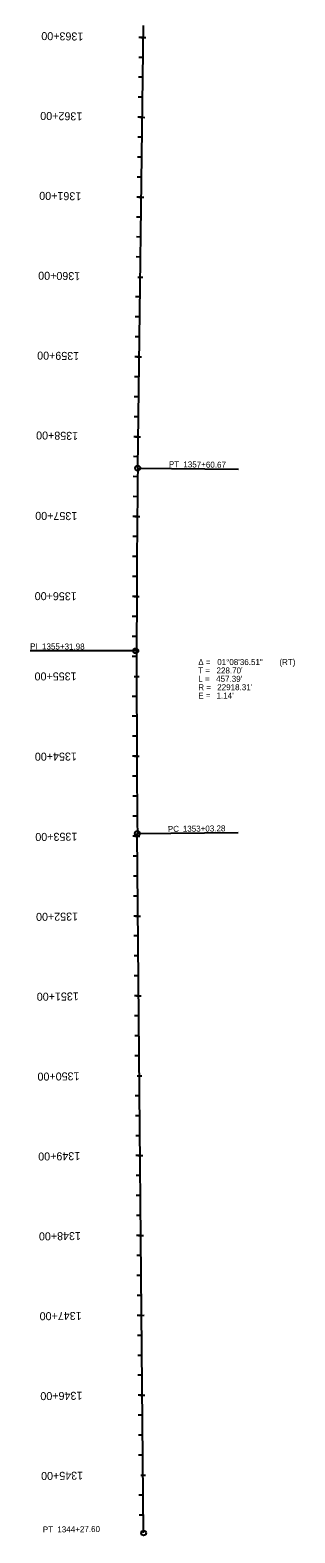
# Model space of a CAD drawing. Extents: x 19548215 to 19548727, y 7547983 to 7562114.
# Drawn here: x 19548243 to 19548574, y 7556426 to 7558308 of the extents above; entities that cross this region are included whole.
import ezdxf

# ---------------------------------------------------------------- set-up
doc = ezdxf.new("R2010")
doc.units = 0
for name, color, linetype in [('Contours Major', 7, 'Continuous'), ('Contours Minor', 7, 'Continuous'), ('Default', 7, 'Continuous'), ('TextAlignment', 7, 'Continuous'), ('TextAlignmentSml', 7, 'Continuous')]:
    doc.layers.add(name, color=color, linetype=linetype)

msp = doc.modelspace()

# ---------------------------------------------------------------- linework, layer by layer
at = {"layer": 'Contours Major'}
for p, q in [((19548384.7, 7558298.7), (19548379.3, 7558298.7)), ((19548383.4, 7558198.7), (19548378, 7558198.7)), ((19548382.1, 7558098.7), (19548376.7, 7558098.8)), ((19548377.8, 7557998.7), (19548383.9, 7557998.6)), ((19548379.5, 7557898.7), (19548374.1, 7557898.8)), ((19548378.2, 7557798.7), (19548372.7, 7557798.8)), ((19548377.1, 7557698.7), (19548371.6, 7557698.8)), ((19548376.5, 7557598.7), (19548371, 7557598.7)), ((19548373.3, 7557498.7), (19548379.4, 7557498.7)), ((19548376.6, 7557398.7), (19548371.1, 7557398.7)), ((19548377.3, 7557298.7), (19548371.8, 7557298.7)), ((19548378.2, 7557198.7), (19548372.7, 7557198.7)), ((19548379.1, 7557098.7), (19548373.6, 7557098.7)), ((19548376.9, 7556998.7), (19548383, 7556998.8)), ((19548380.9, 7556898.7), (19548375.4, 7556898.7)), ((19548381.8, 7556798.7), (19548376.3, 7556798.7)), ((19548382.7, 7556698.7), (19548377.2, 7556698.7)), ((19548383.6, 7556598.7), (19548378.1, 7556598.7)), ((19548381.4, 7556498.7), (19548387.5, 7556498.8))]:
    msp.add_line(p, q, dxfattribs=at)
at = {"layer": 'Contours Minor'}
for p, q in [((19548377.7, 7557759.4), (19548384.9, 7558313.4)), ((19548385.1, 7556426.3), (19548377.2, 7557302))]:
    msp.add_line(p, q, dxfattribs=at)
msp.add_arc((19571294.6, 7557508.5), 22918.3, 179.37292, 180.51639, dxfattribs=at)
at = {"layer": 'Default'}
msp.add_line((19548385.1, 7556426.3), (19548377.2, 7557302), dxfattribs=at)
msp.add_arc((19571294.6, 7557508.5), 22918.3, 179.37292, 180.51639, dxfattribs=at)
at = {"layer": 'TextAlignment'}
for p, q in [((19548377.7, 7557759.4), (19548503.7, 7557758)), ((19548503.7, 7557758), (19548503.7, 7557758)), ((19548375.2, 7557530.7), (19548243.2, 7557530.8)), ((19548243.2, 7557530.8), (19548243.2, 7557530.8)), ((19548377.2, 7557302), (19548503.2, 7557303.1)), ((19548503.2, 7557303.1), (19548503.2, 7557303.1))]:
    msp.add_line(p, q, dxfattribs=at)
for centre in [(19548377.7, 7557759.4), (19548375.2, 7557530.7), (19548377.2, 7557302), (19548385.1, 7556426.3)]:
    msp.add_circle(centre, 3.12, dxfattribs=at)
at = {"layer": 'TextAlignmentSml'}
for p, q in [((19548381.7, 7558298.7), (19548387.8, 7558298.6)), ((19548384.4, 7558273.7), (19548379, 7558273.7)), ((19548384.1, 7558248.7), (19548378.6, 7558248.7)), ((19548383.8, 7558223.7), (19548378.3, 7558223.7)), ((19548380.4, 7558198.7), (19548386.5, 7558198.6)), ((19548383.1, 7558173.7), (19548377.7, 7558173.7)), ((19548382.8, 7558148.7), (19548377.3, 7558148.7)), ((19548382.5, 7558123.7), (19548377, 7558123.8)), ((19548379.1, 7558098.7), (19548385.2, 7558098.6)), ((19548381.8, 7558073.7), (19548376.3, 7558073.8)), ((19548381.5, 7558048.7), (19548376, 7558048.8)), ((19548381.1, 7558023.7), (19548375.7, 7558023.8)), ((19548377.8, 7557998.7), (19548383.9, 7557998.6)), ((19548380.5, 7557973.7), (19548375, 7557973.8)), ((19548380.2, 7557948.7), (19548374.7, 7557948.8)), ((19548379.8, 7557923.7), (19548374.4, 7557923.8)), ((19548376.5, 7557898.7), (19548382.6, 7557898.7)), ((19548379.2, 7557873.7), (19548373.7, 7557873.8)), ((19548378.9, 7557848.7), (19548373.4, 7557848.8)), ((19548378.5, 7557823.7), (19548373.1, 7557823.8)), ((19548375.1, 7557798.7), (19548381.3, 7557798.7)), ((19548377.9, 7557773.7), (19548372.4, 7557773.8)), ((19548377.6, 7557748.7), (19548372.1, 7557748.8)), ((19548377.3, 7557723.7), (19548371.9, 7557723.8)), ((19548374, 7557698.7), (19548380.2, 7557698.7)), ((19548376.9, 7557673.7), (19548371.5, 7557673.8)), ((19548376.7, 7557648.7), (19548371.3, 7557648.7)), ((19548376.6, 7557623.7), (19548371.1, 7557623.7)), ((19548373.4, 7557598.7), (19548379.6, 7557598.7)), ((19548376.4, 7557573.7), (19548370.9, 7557573.7)), ((19548376.4, 7557548.7), (19548370.9, 7557548.7)), ((19548376.3, 7557523.7), (19548370.9, 7557523.7)), ((19548373.3, 7557498.7), (19548379.4, 7557498.7)), ((19548376.3, 7557473.7), (19548370.9, 7557473.7)), ((19548376.4, 7557448.7), (19548370.9, 7557448.7)), ((19548376.5, 7557423.7), (19548371, 7557423.7)), ((19548373.5, 7557398.7), (19548379.6, 7557398.7)), ((19548376.7, 7557373.7), (19548371.3, 7557373.7)), ((19548376.9, 7557348.7), (19548371.4, 7557348.7)), ((19548377.1, 7557323.7), (19548371.6, 7557323.7)), ((19548374.2, 7557298.7), (19548380.3, 7557298.7)), ((19548377.5, 7557273.7), (19548372, 7557273.7)), ((19548377.7, 7557248.7), (19548372.3, 7557248.7)), ((19548378, 7557223.7), (19548372.5, 7557223.7)), ((19548375.1, 7557198.7), (19548381.2, 7557198.7)), ((19548378.4, 7557173.7), (19548372.9, 7557173.7)), ((19548378.6, 7557148.7), (19548373.2, 7557148.7)), ((19548378.9, 7557123.7), (19548373.4, 7557123.7)), ((19548376, 7557098.7), (19548382.1, 7557098.8)), ((19548379.3, 7557073.7), (19548373.8, 7557073.7)), ((19548379.5, 7557048.7), (19548374.1, 7557048.7)), ((19548379.8, 7557023.7), (19548374.3, 7557023.7)), ((19548376.9, 7556998.7), (19548383, 7556998.8)), ((19548380.2, 7556973.7), (19548374.7, 7556973.7)), ((19548380.4, 7556948.7), (19548375, 7556948.7)), ((19548380.7, 7556923.7), (19548375.2, 7556923.7)), ((19548377.8, 7556898.7), (19548383.9, 7556898.8)), ((19548381.1, 7556873.7), (19548375.6, 7556873.7)), ((19548381.3, 7556848.7), (19548375.9, 7556848.7)), ((19548381.6, 7556823.7), (19548376.1, 7556823.7)), ((19548378.7, 7556798.7), (19548384.8, 7556798.8)), ((19548382, 7556773.7), (19548376.5, 7556773.7)), ((19548382.2, 7556748.7), (19548376.8, 7556748.7)), ((19548382.5, 7556723.7), (19548377, 7556723.7)), ((19548379.6, 7556698.7), (19548385.7, 7556698.8)), ((19548382.9, 7556673.7), (19548377.5, 7556673.7)), ((19548383.1, 7556648.7), (19548377.7, 7556648.7)), ((19548383.4, 7556623.7), (19548377.9, 7556623.7)), ((19548380.5, 7556598.7), (19548386.6, 7556598.8)), ((19548383.8, 7556573.7), (19548378.4, 7556573.7)), ((19548384, 7556548.7), (19548378.6, 7556548.7)), ((19548384.3, 7556523.7), (19548378.8, 7556523.7)), ((19548381.4, 7556498.7), (19548387.5, 7556498.8)), ((19548384.7, 7556473.8), (19548379.3, 7556473.7)), ((19548384.9, 7556448.8), (19548379.5, 7556448.7))]:
    msp.add_line(p, q, dxfattribs=at)

# ---------------------------------------------------------------- texts
at = {"layer": 'Contours Major'}
for s, rotation, p in [('1360+00', 179.2501, (19548305.9, 7558004.7)), ('1355+00', 180.0246, (19548301.3, 7557503.7)), ('1350+00', 180.5164, (19548304.9, 7557003.1)), ('1345+00', 180.5164, (19548309.4, 7556503.1))]:
    msp.add_text(s, height=10.02, rotation=rotation, dxfattribs=at).set_placement(p)
at = {"layer": 'TextAlignment'}
for s, rotation, p in [('PT', 359.3729, (19548416.6, 7557760.6)), ('1357+60.67', 359.3729, (19548434.7, 7557760.4)), ('PI ', 359.9447, (19548243.2, 7557532.5)), ('1355+31.98', 359.9447, (19548258.1, 7557532.4)), ('PC', 0.5164, (19548415.4, 7557304)), ('1353+03.28', 0.5164, (19548434.1, 7557304.2)), ('PT', 0.5164, (19548259.1, 7556426.9)), ('1344+27.60', 0.5164, (19548277.3, 7556427))]:
    msp.add_text(s, height=7.5, rotation=rotation, dxfattribs=at).set_placement(p)
for s, p in [('Δ = ', (19548453.4, 7557512.9)), ('01°08\'36.51"', (19548477.1, 7557512.9)), (' (RT)', (19548552, 7557512.9)), ('T = ', (19548453.4, 7557502.4)), ('L = ', (19548453.4, 7557491.9)), ("457.39'", (19548475.7, 7557491.9)), ("228.70'", (19548476.2, 7557502.4)), ('R = ', (19548453.4, 7557481.4)), ('E = ', (19548453.4, 7557470.9)), ("1.14'", (19548476.2, 7557470.9)), ("22918.31'", (19548477.1, 7557481.4))]:
    msp.add_text(s, height=7.5, dxfattribs=at).set_placement(p)
at = {"layer": 'TextAlignmentSml'}
for s, rotation, p in [('1363+00', 179.2501, (19548309.8, 7558304.7)), ('1362+00', 179.2501, (19548308.5, 7558204.7)), ('1361+00', 179.2501, (19548307.2, 7558104.7)), ('1360+00', 179.2501, (19548305.9, 7558004.7)), ('1359+00', 179.2501, (19548304.6, 7557904.7)), ('1358+00', 179.2501, (19548303.3, 7557804.7)), ('1357+00', 179.5246, (19548302.2, 7557704.3)), ('1356+00', 179.7746, (19548301.5, 7557604)), ('1355+00', 180.0246, (19548301.3, 7557503.7)), ('1354+00', 180.2746, (19548301.6, 7557403.4)), ('1353+00', 180.5164, (19548302.2, 7557303.1)), ('1352+00', 180.5164, (19548303.1, 7557203.1)), ('1351+00', 180.5164, (19548304, 7557103.1)), ('1350+00', 180.5164, (19548304.9, 7557003.1)), ('1349+00', 180.5164, (19548305.8, 7556903.1)), ('1348+00', 180.5164, (19548306.7, 7556803.1)), ('1347+00', 180.5164, (19548307.6, 7556703.1)), ('1346+00', 180.5164, (19548308.5, 7556603.1)), ('1345+00', 180.5164, (19548309.4, 7556503.1))]:
    msp.add_text(s, height=10.02, rotation=rotation, dxfattribs=at).set_placement(p)

doc.saveas('drawing.dxf')
